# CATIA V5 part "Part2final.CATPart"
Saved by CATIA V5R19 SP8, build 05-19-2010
Part number: Part2
Bounding box of the stored display mesh (mm): x 0 to 20, y -50 to 50, z -50 to 50
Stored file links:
  D:\Dropbox\CIAO82010_JCF\SAMADI\7-SAMADI\Part2final.CATPart
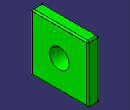
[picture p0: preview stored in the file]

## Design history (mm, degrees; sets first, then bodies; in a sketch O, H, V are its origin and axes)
Parameters
  LENGTH = 10 mm
Body1 (main body)
  Sketch1 on yz-plane, origin (0, 0, 0), H (0, 1, 0), V (0, 0, 1)
    line L1 (-50, 50) -> (50, 50)
    line L2 (50, 50) -> (50, -50)
    line L3 (50, -50) -> (-50, -50)
    line L4 (-50, -50) -> (-50, 50)
    length L2 = 100 {= LENGTH *10}
    length L3 = 100 {= LENGTH *10}
    distance L2 V = 50 {= LENGTH *5}
    distance L3 H = 50 {= LENGTH *5}
    horizontal: L1 H, L3 H
    vertical: L2 V, L4 V
  Pad1: profile Sketch1, direction (1, 0, 0), length 20 {= LENGTH *2}
  Sketch2 on end face of Pad1, origin (20, 5.1215, 23.6096), H (0, 1, 0), V (0, 0, 1)
    point P1 (-5.1215, -23.6096)
    reference projected line E1 (-55.1215, -73.6096) -> (44.8785, -73.6096) from edge [face of Pad1 from Sketch1.L3 | end face of Pad1]
    reference projected line E2 (-55.1215, 26.3904) -> (-55.1215, -73.6096) from edge [face of Pad1 from Sketch1.L4 | end face of Pad1]
    distance P1 E1 = 50 {= LENGTH *5}
    distance P1 E2 = 50 {= LENGTH *5}
  Hole1: placed by Sketch2, at (20, 0, 0) direction (-1, 0, 0), diameter 20 {= LENGTH *2}, up to start face of Pad1, offset 0 {= LENGTH *0}, type TaperedType, Diameter 20 {= LENGTH *2}, Sketch Sketch2, Profile a sketch, ThreadDepth 10, DiameterThread 11, Pas 1, Angle 40
  Fillet1: radius 2.5 {= LENGTH *0.25}, on edge [face of Pad1 from Sketch1.L3 | end face of Pad1]; edge [start face of Pad1 | face of Pad1 from Sketch1.L3]; edge [start face of Pad1 | face of Pad1 from Sketch1.L4]; edge [face of Pad1 from Sketch1.L4 | end face of Pad1]; edge [start face of Pad1 | face of Pad1 from Sketch1.L1]; edge [face of Pad1 from Sketch1.L1 | end face of Pad1]; edge [face of Pad1 from Sketch1.L1 | face of Pad1 from Sketch1.L2]; edge [face of Pad1 from Sketch1.L2 | end face of Pad1]; edge [start face of Pad1 | face of Pad1 from Sketch1.L2]; edge [face of Pad1 from Sketch1.L4 | face of Pad1 from Sketch1.L1]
